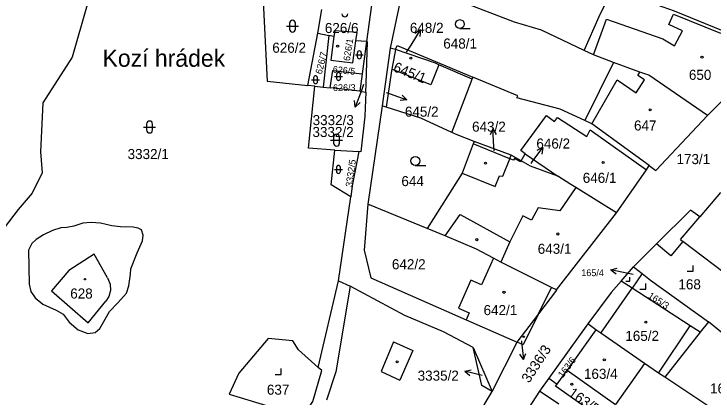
# Model space of a CAD drawing. Extents: x -600849 to -599899, y -1204328 to -1203436.
# Drawn here: x -600587.3 to -600469.3, y -1203635.4 to -1203570.8 of the extents above; entities that cross this region are included whole.
import ezdxf

# ---------------------------------------------------------------- set-up
doc = ezdxf.new("R2010")
doc.units = 0
for name, color, linetype in [('Vrstva 1', 7, 'Continuous'), ('Vrstva 2', 7, 'Continuous'), ('Vrstva 3', 7, 'Continuous'), ('Vrstva 4', 7, 'Continuous'), ('Vrstva 5', 7, 'Continuous'), ('Vrstva 7', 7, 'Continuous')]:
    doc.layers.add(name, color=color, linetype=linetype)

msp = doc.modelspace()

# ---------------------------------------------------------------- linework, layer by layer
at = {"layer": 'Vrstva 1'}
for p, q in [((-600521.35, -1203564.72), (-600523.82, -1203576.55)), ((-600488.58, -1203571.21), (-600486.26, -1203566.43)), ((-600526.97, -1203569.31), (-600527.85, -1203575.45)), ((-600536.07, -1203574.02), (-600535.37, -1203570.01)), ((-600491.12, -1203576.92), (-600488.58, -1203571.21)), ((-600537.72, -1203582.87), (-600536.07, -1203574.02)), ((-600536.07, -1203574.02), (-600534.19, -1203574.39)), ((-600534.19, -1203574.39), (-600535.17, -1203583.14)), ((-600533.32, -1203574.56), (-600534.19, -1203574.39)), ((-600527.85, -1203575.45), (-600529.61, -1203575.29)), ((-600527.85, -1203575.45), (-600528.56, -1203580.89)), ((-600523.82, -1203576.55), (-600525.17, -1203586.26)), ((-600522.94, -1203576.75), (-600523.82, -1203576.55)), ((-600486.13, -1203578.96), (-600491, -1203588.77)), ((-600528.56, -1203580.89), (-600528.97, -1203583.83)), ((-600513.41, -1203590.76), (-600510.02, -1203581.77)), ((-600509.91, -1203581.42), (-600510.02, -1203581.77)), ((-600536.53, -1203582.99), (-600537.72, -1203582.87)), ((-600536.53, -1203582.99), (-600535.17, -1203583.14)), ((-600535.17, -1203583.14), (-600533.94, -1203583.27)), ((-600528.97, -1203583.83), (-600533.94, -1203583.27)), ((-600527.95, -1203583.96), (-600527.9, -1203582.52)), ((-600528.97, -1203583.83), (-600527.95, -1203583.96)), ((-600527.95, -1203583.96), (-600528.1, -1203588.03)), ((-600525.17, -1203586.26), (-600527.59, -1203602.88)), ((-600524.5, -1203586.5), (-600525.17, -1203586.26)), ((-600528.1, -1203588.03), (-600528.78, -1203594.03)), ((-600489.82, -1203589.32), (-600491, -1203588.77)), ((-600480.11, -1203596.36), (-600489.82, -1203589.32)), ((-600512.5, -1203591.2), (-600513.41, -1203590.76)), ((-600509.65, -1203592.28), (-600512.5, -1203591.2)), ((-600509.65, -1203592.28), (-600509.8, -1203592.67)), ((-600503.41, -1203594.63), (-600509.65, -1203592.28)), ((-600533.15, -1203593.75), (-600529.15, -1203594)), ((-600528.78, -1203594.03), (-600529.15, -1203594)), ((-600501.75, -1203595.57), (-600503.41, -1203594.63)), ((-600500.13, -1203596.49), (-600501.75, -1203595.57)), ((-600495.51, -1203598.16), (-600500.13, -1203596.49)), ((-600532.56, -1203615.8), (-600530.5, -1203601.63)), ((-600517.58, -1203606.99), (-600527.59, -1203602.88)), ((-600495.78, -1203617.36), (-600485.66, -1203604.37)), ((-600473.16, -1203603.87), (-600478.86, -1203609.57)), ((-600514.53, -1203608.24), (-600517.58, -1203606.99)), ((-600509.24, -1203610.5), (-600514.53, -1203608.24)), ((-600506.42, -1203612.01), (-600509.24, -1203610.5)), ((-600478.86, -1203609.57), (-600482.78, -1203613.48)), ((-600484.83, -1203615.85), (-600482.78, -1203613.48)), ((-600482.78, -1203613.48), (-600481.33, -1203614.59)), ((-600527.07, -1203615.3), (-600510.99, -1203622.38)), ((-600481.33, -1203614.59), (-600483.01, -1203617.03)), ((-600535.96, -1203630.46), (-600532.56, -1203615.8)), ((-600532.56, -1203615.8), (-600530.6, -1203616.71)), ((-600484.83, -1203615.85), (-600486.52, -1203617.79)), ((-600483.01, -1203617.03), (-600484.83, -1203615.85)), ((-600521.37, -1203621.69), (-600530.6, -1203616.71)), ((-600498.94, -1203621.64), (-600495.71, -1203617.4)), ((-600495.71, -1203617.4), (-600495.78, -1203617.36)), ((-600486.52, -1203617.79), (-600490.5, -1203623.06)), ((-600510.99, -1203622.38), (-600502.39, -1203626.17)), ((-600502.39, -1203626.17), (-600498.94, -1203621.64)), ((-600490.5, -1203623.06), (-600497.06, -1203632.24)), ((-600489.11, -1203624.07), (-600490.5, -1203623.06)), ((-600470.13, -1203622.73), (-600471.52, -1203624.5)), ((-600461.07, -1203630.12), (-600470.13, -1203622.73)), ((-600489.11, -1203624.07), (-600493.96, -1203630.88)), ((-600471.52, -1203624.5), (-600477.46, -1203632.09)), ((-600509.8, -1203627.06), (-600506.63, -1203634.51)), ((-600506.63, -1203634.51), (-600502.39, -1203626.17)), ((-600480.89, -1203629.76), (-600485.82, -1203636.68)), ((-600495.64, -1203633.24), (-600493.96, -1203630.88)), ((-600493.96, -1203630.88), (-600485.82, -1203636.68)), ((-600497.06, -1203632.24), (-600498.63, -1203634.44)), ((-600497.06, -1203632.24), (-600495.64, -1203633.24)), ((-600461.92, -1203642.39), (-600477.46, -1203632.09)), ((-600498.63, -1203634.44), (-600504.83, -1203644.05))]:
    msp.add_line(p, q, dxfattribs=at)
for points in [[(-600567.71, -1203535.68), (-600568.88, -1203541.35), (-600570.78, -1203553), (-600572.53, -1203560.77), (-600577.53, -1203578.08), (-600582.45, -1203585.75), (-600582.83, -1203594.05), (-600582.58, -1203597.57), (-600584.26, -1203601.02), (-600586.62, -1203603.76), (-600592.16, -1203610.92), (-600599.38, -1203621.05), (-600601.73, -1203624.09), (-600605.79, -1203627.61)], [(-600459.28, -1203578.17), (-600460.53, -1203577.18), (-600467.84, -1203573.55), (-600475.84, -1203570.31), (-600482.56, -1203567.9), (-600486.26, -1203566.43)], [(-600545.25, -1203568.67), (-600544.59, -1203582.14), (-600537.72, -1203582.87)], [(-600491.12, -1203576.92), (-600498.27, -1203573.51), (-600502.86, -1203572.19), (-600512.22, -1203568.54)], [(-600529.61, -1203575.29), (-600529.42, -1203573.89), (-600533.19, -1203573.63), (-600533.32, -1203574.56)], [(-600533.32, -1203574.56), (-600533.87, -1203578.6), (-600530.12, -1203579.01), (-600529.61, -1203575.29)], [(-600527.9, -1203582.52), (-600527.68, -1203575.48), (-600527.85, -1203575.45)], [(-600522.94, -1203576.75), (-600522.64, -1203576.1), (-600515.5, -1203579.07), (-600509.91, -1203581.42)], [(-600522.94, -1203576.75), (-600523.58, -1203580.1), (-600523.63, -1203580.37), (-600524.5, -1203586.5)], [(-600510.02, -1203581.77), (-600515.61, -1203579.35), (-600516.17, -1203579.1), (-600522.94, -1203576.75)], [(-600486.13, -1203578.96), (-600489.53, -1203577.68), (-600491.12, -1203576.92)], [(-600470.3, -1203587.91), (-600460.35, -1203578.05), (-600459.28, -1203578.17)], [(-600470.3, -1203587.91), (-600480.18, -1203581.1), (-600481.69, -1203580.6), (-600486.13, -1203578.96)], [(-600533.94, -1203583.27), (-600533.52, -1203580.34), (-600528.56, -1203580.89)], [(-600491, -1203588.77), (-600495.13, -1203586.86), (-600502.45, -1203584.96), (-600502.3, -1203584.58), (-600509.91, -1203581.42)], [(-600533.15, -1203593.75), (-600537.64, -1203593.44), (-600536.53, -1203582.99)], [(-600513.41, -1203590.76), (-600518.65, -1203588.36), (-600524.5, -1203586.5)], [(-600480.11, -1203596.36), (-600478.99, -1203597.18), (-600470.3, -1203587.91)], [(-600509.8, -1203592.67), (-600511.71, -1203597.67), (-600517.58, -1203606.99)], [(-600501.75, -1203595.57), (-600501.83, -1203595.71), (-600502.85, -1203595.16), (-600503.03, -1203595.48), (-600503.65, -1203595.22), (-600509.8, -1203592.67)], [(-600530.5, -1203601.63), (-600533.77, -1203599.6), (-600533.15, -1203593.75)], [(-600529.15, -1203594), (-600530.23, -1203599.78), (-600530.5, -1203601.63)], [(-600501.75, -1203595.57), (-600501.03, -1203594.4), (-600495.51, -1203598.16)], [(-600485.66, -1203604.37), (-600480.59, -1203597.09), (-600480.11, -1203596.36)], [(-600485.66, -1203604.37), (-600492.52, -1203600.06), (-600493.32, -1203599.55), (-600495.51, -1203598.16)], [(-600468.09, -1203600.92), (-600471.57, -1203605.02), (-600473.16, -1203603.87)], [(-600527.59, -1203602.88), (-600528.22, -1203610.64), (-600527.07, -1203615.3)], [(-600569.32, -1203606.72), (-600570.8, -1203606.52), (-600572.72, -1203606.1), (-600574.31, -1203605.99), (-600575.68, -1203606.1), (-600577.2, -1203606.57), (-600578.41, -1203606.83), (-600579.41, -1203606.9), (-600580.84, -1203607.32), (-600582.32, -1203608.05), (-600583.56, -1203608.84), (-600584.33, -1203609.53), (-600584.87, -1203610.62), (-600584.75, -1203616.38), (-600584.48, -1203617.62), (-600583.75, -1203618.7), (-600582.47, -1203619.74), (-600580.23, -1203620.75), (-600579.03, -1203621.45), (-600577.99, -1203622.8), (-600576.52, -1203624.11), (-600574.86, -1203624.73), (-600573.62, -1203624.54), (-600572.85, -1203623.84), (-600571.92, -1203622.3), (-600571.19, -1203621.02), (-600569.8, -1203619.51), (-600568.33, -1203617.89), (-600567.94, -1203616.69), (-600567.67, -1203614.72), (-600567.59, -1203613.79), (-600566.51, -1203611.09), (-600565.66, -1203609.05), (-600565.54, -1203608.11), (-600565.79, -1203607.24), (-600566.34, -1203606.94), (-600567.2, -1203606.79), (-600569.32, -1203606.72)], [(-600456.16, -1203616.45), (-600458.62, -1203614.64), (-600463.06, -1203611.14), (-600465.85, -1203615.69), (-600474.44, -1203609.18), (-600476.47, -1203611.59), (-600478.86, -1203609.57)], [(-600506.42, -1203612.01), (-600508.41, -1203616.52), (-600510.21, -1203615.73), (-600512.28, -1203620.45), (-600510.49, -1203621.24), (-600510.99, -1203622.38)], [(-600495.78, -1203617.36), (-600496.63, -1203616.94), (-600505.16, -1203612.68), (-600506.42, -1203612.01)], [(-600481.33, -1203614.59), (-600479.91, -1203615.68), (-600470.13, -1203622.73)], [(-600530.6, -1203616.71), (-600533.03, -1203631.2), (-600534.57, -1203635.98)], [(-600471.52, -1203624.5), (-600473.23, -1203623.39), (-600483.01, -1203617.03)], [(-600509.8, -1203627.06), (-600514.86, -1203624.45), (-600521.37, -1203621.69)], [(-600498.94, -1203621.64), (-600501.38, -1203626.61), (-600502.39, -1203626.17)], [(-600480.89, -1203629.76), (-600488.27, -1203624.67), (-600489.11, -1203624.07)], [(-600535.96, -1203630.46), (-600539.29, -1203627.47), (-600540.29, -1203625.92), (-600544.43, -1203625.57), (-600549.38, -1203631.43), (-600550.98, -1203634.95), (-600544.72, -1203636.85), (-600545.1, -1203637.43)], [(-600506.63, -1203634.51), (-600508.36, -1203633.49), (-600509.8, -1203627.06)], [(-600540.03, -1203640.86), (-600536.89, -1203636.19), (-600535.34, -1203630.96), (-600535.96, -1203630.46)], [(-600477.46, -1203632.09), (-600478.53, -1203631.38), (-600480.89, -1203629.76)], [(-600487.37, -1203638.87), (-600487.73, -1203639.37), (-600495.91, -1203633.62), (-600495.64, -1203633.24)], [(-600527.86, -1203654.9), (-600522.41, -1203658.19), (-600511.68, -1203642.2), (-600509.04, -1203638.54), (-600506.63, -1203634.51)]]:
    msp.add_lwpolyline(points, dxfattribs=at)
at = {"layer": 'Vrstva 3'}
for p, q in [((-600541.32, -1203572.83), (-600539.32, -1203572.83)), ((-600540.82, -1203572.33), (-600540.82, -1203573.33)), ((-600539.82, -1203573.33), (-600539.82, -1203572.33)), ((-600512.07, -1203573.24), (-600510.32, -1203573.24)), ((-600529.38, -1203577.33), (-600529.38, -1203578.01)), ((-600528.7, -1203578.01), (-600528.7, -1203577.33)), ((-600529.71, -1203577.67), (-600528.37, -1203577.67)), ((-600532.89, -1203580.98), (-600532.89, -1203581.65)), ((-600532.21, -1203581.65), (-600532.21, -1203580.98)), ((-600537.1, -1203581.88), (-600535.76, -1203581.88)), ((-600536.77, -1203581.54), (-600536.77, -1203582.22)), ((-600536.09, -1203582.22), (-600536.09, -1203581.54)), ((-600533.22, -1203581.31), (-600531.88, -1203581.31)), ((-600564.94, -1203589.36), (-600564.94, -1203590.36)), ((-600563.94, -1203590.36), (-600563.94, -1203589.36)), ((-600565.44, -1203589.86), (-600563.44, -1203589.86)), ((-600533.38, -1203591.57), (-600533.38, -1203592.57)), ((-600532.38, -1203592.57), (-600532.38, -1203591.57)), ((-600533.88, -1203592.07), (-600531.88, -1203592.07)), ((-600519.59, -1203596.33), (-600517.84, -1203596.33)), ((-600533.24, -1203597.01), (-600531.9, -1203597.01)), ((-600532.91, -1203596.68), (-600532.91, -1203597.35)), ((-600532.23, -1203597.35), (-600532.23, -1203596.68)), ((-600472.72, -1203614.21), (-600472.72, -1203613.21)), ((-600483.41, -1203615.89), (-600483.41, -1203615.22)), ((-600473.72, -1203614.21), (-600472.72, -1203614.21)), ((-600484.08, -1203615.89), (-600483.41, -1203615.89)), ((-600480.7, -1203617.25), (-600480.7, -1203616.25)), ((-600481.7, -1203617.25), (-600480.7, -1203617.25)), ((-600542.25, -1203631.62), (-600542.25, -1203630.62)), ((-600543.25, -1203631.62), (-600542.25, -1203631.62))]:
    msp.add_line(p, q, dxfattribs=at)
for centre in [(-600512.07, -1203572.49), (-600519.59, -1203595.58)]:
    msp.add_circle(centre, 0.75, dxfattribs=at)
for centre, radius, start, end in [((-600531.48, -1203570.77), 0.5, 180, 359.9879), ((-600540.32, -1203572.33), 0.5, 0, 180), ((-600540.32, -1203573.33), 0.5, 180, 359.9879), ((-600529.04, -1203577.34), 0.335, 0, 180), ((-600529.04, -1203578.01), 0.335, 180, 359.9879), ((-600532.55, -1203580.98), 0.335, 0, 180), ((-600536.43, -1203581.55), 0.335, 0, 180), ((-600536.43, -1203582.22), 0.335, 180, 359.9879), ((-600532.55, -1203581.65), 0.335, 180, 359.9879), ((-600564.44, -1203589.36), 0.5, 0, 180), ((-600564.44, -1203590.36), 0.5, 180, 359.9879), ((-600532.88, -1203591.57), 0.5, 0, 180), ((-600532.88, -1203592.57), 0.5, 180, 359.9879), ((-600532.57, -1203596.68), 0.335, 0, 180), ((-600532.57, -1203597.35), 0.335, 180, 359.9879)]:
    msp.add_arc(centre, radius, start, end, dxfattribs=at)
at = {"layer": 'Vrstva 4'}
for p, q in [((-600489.53, -1203577.68), (-600487.3, -1203571.66)), ((-600487.3, -1203571.66), (-600477.8, -1203574.96)), ((-600476.79, -1203572.57), (-600476.04, -1203570.79)), ((-600476.04, -1203570.79), (-600468.07, -1203574.01)), ((-600474.48, -1203573.6), (-600476.79, -1203572.57)), ((-600475.87, -1203576.13), (-600474.48, -1203573.6)), ((-600477.8, -1203574.96), (-600475.87, -1203576.13)), ((-600482.01, -1203581.14), (-600481.69, -1203580.6)), ((-600480.89, -1203581.91), (-600482.01, -1203581.14)), ((-600489.82, -1203589.32), (-600485.53, -1203581.91)), ((-600485.53, -1203581.91), (-600482.32, -1203584.11)), ((-600482.32, -1203584.11), (-600480.89, -1203581.91)), ((-600501.78, -1203593.82), (-600497.45, -1203587.94)), ((-600497.45, -1203587.94), (-600496.09, -1203588.93)), ((-600496.09, -1203588.93), (-600495.57, -1203588.24)), ((-600495.57, -1203588.24), (-600490.66, -1203591.47)), ((-600490.66, -1203591.47), (-600490.09, -1203590.34)), ((-600490.09, -1203590.34), (-600480.59, -1203597.09)), ((-600501.03, -1203594.4), (-600501.78, -1203593.82)), ((-600504.82, -1203598.15), (-600503.65, -1203595.22)), ((-600503.65, -1203595.22), (-600503.41, -1203594.63)), ((-600511.71, -1203597.67), (-600506.1, -1203599.92)), ((-600506.1, -1203599.92), (-600505.36, -1203598.08)), ((-600505.36, -1203598.08), (-600504.82, -1203598.15)), ((-600492.52, -1203600.06), (-600495.18, -1203604.03)), ((-600498.88, -1203603.51), (-600499.97, -1203605.6)), ((-600495.18, -1203604.03), (-600498.88, -1203603.51)), ((-600514.53, -1203608.24), (-600512.03, -1203604.6)), ((-600512.03, -1203604.6), (-600503.63, -1203609.26)), ((-600501.44, -1203604.83), (-600503.63, -1203609.26)), ((-600499.97, -1203605.6), (-600501.44, -1203604.83)), ((-600474.84, -1203608.87), (-600471.57, -1203605.02)), ((-600503.63, -1203609.26), (-600505.16, -1203612.68)), ((-600474.84, -1203608.87), (-600474.44, -1203609.18)), ((-600573.82, -1203611.32), (-600578.05, -1203614.06)), ((-600571.53, -1203615.31), (-600573.82, -1203611.32)), ((-600578.05, -1203614.06), (-600581, -1203617.53)), ((-600571.53, -1203615.31), (-600571.09, -1203616.36)), ((-600571.09, -1203616.36), (-600571.03, -1203617.46)), ((-600581, -1203617.53), (-600574.83, -1203622.93)), ((-600571.03, -1203617.46), (-600571.3, -1203618.45)), ((-600498.94, -1203621.64), (-600496.63, -1203616.94)), ((-600488.27, -1203624.67), (-600483.01, -1203617.03)), ((-600571.3, -1203618.45), (-600571.82, -1203619.25)), ((-600574.83, -1203622.93), (-600571.82, -1203619.25)), ((-600478.53, -1203631.38), (-600473.23, -1203623.39)), ((-600523.26, -1203626.12), (-600525.33, -1203631.11)), ((-600523.26, -1203626.12), (-600519.99, -1203627.59)), ((-600519.99, -1203627.59), (-600522.2, -1203632.57)), ((-600525.33, -1203631.11), (-600522.2, -1203632.57)), ((-600495.36, -1203636.64), (-600498.63, -1203634.44))]:
    msp.add_line(p, q, dxfattribs=at)
msp.add_lwpolyline([(-600515.61, -1203579.35), (-600516.97, -1203582.74), (-600523.58, -1203580.1)], dxfattribs=at)
at = {"layer": 'Vrstva 5'}
for centre, radius in [((-600532.7, -1203576.2), 0.175), ((-600520.34, -1203578.25), 0.175), ((-600471.21, -1203578.07), 0.175), ((-600479.96, -1203586.95), 0.175), ((-600507.73, -1203595.95), 0.175), ((-600487.88, -1203595.84), 0.175), ((-600495.55, -1203607.91), 0.175), ((-600509.21, -1203608.87), 0.175), ((-600575.36, -1203615.54), 0.117), ((-600504.62, -1203617.75), 0.175), ((-600480.7, -1203622.81), 0.175), ((-600501.29, -1203625.25), 0.117), ((-600522.64, -1203629.49), 0.175), ((-600487.69, -1203629.15), 0.175), ((-600493.17, -1203633.28), 0.175)]:
    msp.add_circle(centre, radius, dxfattribs=at)
at = {"layer": 'Vrstva 7'}
for p, q in [((-600520.31, -1203576.02), (-600518.72, -1203573.48)), ((-600518.72, -1203573.48), (-600519.68, -1203574.06)), ((-600518.72, -1203573.48), (-600518.83, -1203574.59)), ((-600521.06, -1203577.22), (-600520.31, -1203576.02)), ((-600528.33, -1203582.67), (-600528.7, -1203583.67)), ((-600528.7, -1203583.67), (-600529.73, -1203586.49)), ((-600524.5, -1203584.02), (-600523.85, -1203584.26)), ((-600523.85, -1203584.26), (-600521.03, -1203585.29)), ((-600521.03, -1203585.29), (-600521.8, -1203584.47)), ((-600529.73, -1203586.49), (-600529.85, -1203585.38)), ((-600529.73, -1203586.49), (-600528.91, -1203585.72)), ((-600521.03, -1203585.29), (-600522.14, -1203585.41)), ((-600506.49, -1203590.14), (-600506.94, -1203591.17)), ((-600506.33, -1203593.14), (-600506.49, -1203590.14)), ((-600506.49, -1203590.14), (-600505.94, -1203591.12)), ((-600506.29, -1203593.89), (-600506.33, -1203593.14)), ((-600499.86, -1203595.74), (-600498.05, -1203593.34)), ((-600498.05, -1203593.34), (-600499.06, -1203593.84)), ((-600498.05, -1203593.34), (-600498.26, -1203594.44)), ((-600500.05, -1203595.99), (-600499.86, -1203595.74)), ((-600486.59, -1203613.95), (-600485.51, -1203613.66)), ((-600483.66, -1203614.57), (-600486.59, -1203613.95)), ((-600486.59, -1203613.95), (-600485.72, -1203614.64)), ((-600482.81, -1203614.75), (-600483.66, -1203614.57)), ((-600501.67, -1203625.97), (-600501.65, -1203626.13)), ((-600501.65, -1203626.13), (-600501.34, -1203629.11)), ((-600501.34, -1203629.11), (-600501.94, -1203628.17)), ((-600501.34, -1203629.11), (-600500.94, -1203628.07)), ((-600511.23, -1203631.06), (-600510.14, -1203630.82)), ((-600508.32, -1203631.79), (-600511.23, -1203631.06)), ((-600511.23, -1203631.06), (-600510.38, -1203631.79))]:
    msp.add_line(p, q, dxfattribs=at)

# ---------------------------------------------------------------- texts
at = {"layer": 'Vrstva 2'}
for s, height, p in [('626/6', 1.7, (-600534.86, -1203574)), ('648/2', 1.7, (-600520.51, -1203573.97)), ('648/1', 1.7, (-600514.87, -1203576.62)), ('626/2', 1.7, (-600543.73, -1203577.33)), ('650', 1.7, (-600473.42, -1203581.9)), ('626/3', 1.14, (-600533.49, -1203583.78)), ('645/2', 1.7, (-600521.35, -1203588.12)), ('3332/3', 1.7, (-600536.92, -1203589.54)), ('643/2', 1.7, (-600510.01, -1203590.65)), ('647', 1.7, (-600482.68, -1203590.45)), ('3332/2', 1.7, (-600536.95, -1203591.55)), ('646/2', 1.7, (-600499.16, -1203593.5)), ('3332/1', 1.7, (-600568.15, -1203595.27)), ('173/1', 1.7, (-600475.51, -1203596.12)), ('646/1', 1.7, (-600491.33, -1203599.29)), ('644', 1.7, (-600521.94, -1203599.84)), ('643/1', 1.7, (-600498.93, -1203611.26)), ('642/2', 1.7, (-600523.54, -1203613.87)), ('165/4', 1.14, (-600491.58, -1203615.03)), ('168', 1.7, (-600475.19, -1203617.26)), ('628', 1.7, (-600577.83, -1203618.81)), ('642/1', 1.7, (-600508.07, -1203621.61)), ('165/2', 1.7, (-600484.15, -1203625.96)), ('163/4', 1.7, (-600491.13, -1203632.37)), ('3335/2', 1.7, (-600519.2, -1203632.67)), ('165/1', 1.7, (-600469.85, -1203634.82)), ('637', 1.7, (-600544.64, -1203635.04))]:
    msp.add_text(s, height=height, dxfattribs=at).set_placement(p)
for s, height, rotation, p in [('626/1', 1.14, 81, (-600530.64, -1203578.78)), ('626/7', 1.14, 76, (-600535.38, -1203581.03)), ('626/5', 1.14, 354, (-600533.58, -1203580.66)), ('645/1', 1.7, 338, (-600523.45, -1203580.39)), ('3332/5', 1.14, 82, (-600530.25, -1203600.04)), ('165/3', 1.14, 327, (-600480.43, -1203618.6)), ('3336/3', 1.7, 57, (-600500.38, -1203633.18)), ('163/6', 1.14, 53, (-600494.7, -1203632.28)), ('163/5', 1.7, 325, (-600493.9, -1203635.1))]:
    msp.add_text(s, height=height, rotation=rotation, dxfattribs=at).set_placement(p)
at = {"layer": 'Vrstva 7'}
msp.add_text('Kozí hrádek', height=2.9, dxfattribs=at).set_placement((-600572.38, -1203579.69))

doc.saveas('drawing.dxf')
